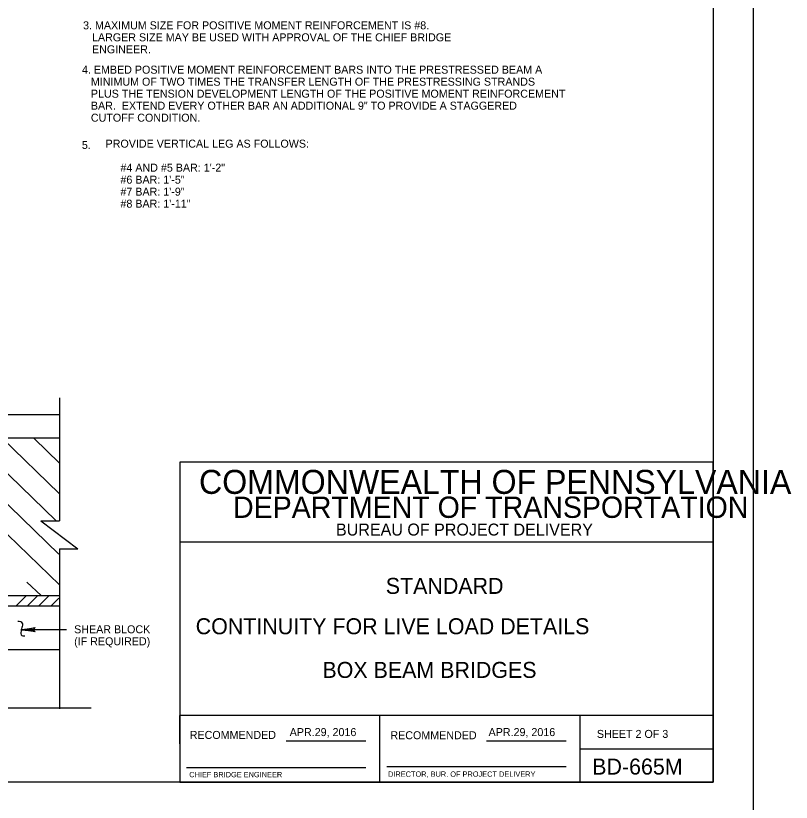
# Model space of a CAD drawing. Extents: x 641517 to 642372, y 298537 to 300319.
# Drawn here: x 642081.6 to 642372.3, y 299138.1 to 299433 of the extents above; entities that cross this region are included whole.
import ezdxf

# ---------------------------------------------------------------- set-up
doc = ezdxf.new("R2010")
doc.units = 0
for name, color, linetype in [('1', 7, 'Continuous'), ('2', 7, 'Continuous'), ('3', 7, 'Continuous'), ('PLT-BNDY', 7, 'Continuous')]:
    doc.layers.add(name, color=color, linetype=linetype)

msp = doc.modelspace()

# ---------------------------------------------------------------- linework, layer by layer
at = {"layer": '1'}
msp.add_spline([(642082.42, 299206.01), (642083.39, 299205.93), (642083.91, 299205.43), (642084.12, 299204.52), (642083.85, 299203.66), (642083.67, 299202.74), (642083.52, 299201.83), (642083.62, 299200.92), (642084.3, 299200.52), (642085.03, 299200.52)], degree=3, dxfattribs=at)
at = {"layer": '2'}
for p, q in [((642343.05, 299709.62), (642343.05, 299145.62)), ((642097.96, 299289.82), (642097.96, 299243.68)), ((641895.27, 299283.53), (642097.96, 299283.53)), ((642097.96, 299274.67), (642037.19, 299274.67)), ((642097.96, 299219.62), (642041.23, 299274.54)), ((642097.79, 299231.2), (642052.95, 299274.61)), ((642096.7, 299243.67), (642064.74, 299274.6)), ((642097.94, 299253.88), (642076.56, 299274.58)), ((642098.01, 299265.23), (642088.45, 299274.48)), ((642343.05, 299265.62), (642143.05, 299265.62)), ((642143.05, 299265.62), (642143.05, 299145.62)), ((642343.05, 299145.62), (642343.05, 299265.62)), ((642091.06, 299243.68), (642097.96, 299243.68)), ((642091.06, 299243.68), (642104.86, 299233.18)), ((642097.96, 299233.18), (642097.96, 299173.17)), ((642097.96, 299233.18), (642104.86, 299233.18)), ((642343.05, 299235.62), (642143.05, 299235.62)), ((642091.1, 299215.64), (642085.77, 299220.69)), ((642037.19, 299215.64), (642097.96, 299215.64)), ((642081.76, 299211.74), (642085.66, 299215.64)), ((642086, 299211.74), (642089.9, 299215.64)), ((642090.24, 299211.74), (642094.14, 299215.64)), ((642094.87, 299211.74), (642097.8, 299214.67)), ((642041.09, 299211.74), (642097.96, 299211.74)), ((642100.61, 299202.83), (642084.05, 299202.83)), ((641895.27, 299195.43), (642097.96, 299195.43)), ((642007.73, 299173.52), (642109.86, 299173.52)), ((642343.05, 299170.62), (642143.05, 299170.62)), ((642143.05, 299160.05), (642143.05, 299170.62)), ((642218.05, 299145.62), (642218.05, 299170.62)), ((642293.05, 299170.62), (642293.05, 299145.62)), ((642183.01, 299161.12), (642212.78, 299161.12)), ((642258.01, 299161.12), (642287.92, 299161.12)), ((642293.05, 299158.12), (642343.05, 299158.12)), ((642145.55, 299151.12), (642212.78, 299151.12)), ((642220.67, 299151.5), (642287.92, 299151.5)), ((642343.05, 299145.62), (641557.05, 299145.62)), ((642143.05, 299145.62), (642343.05, 299145.62))]:
    msp.add_line(p, q, dxfattribs=at)
msp.add_lwpolyline([(642088.66, 299202.25), (642088.49, 299202.58), (642084.05, 299202.83), (642088.66, 299202.25), (642088.9, 299202.04), (642084.05, 299202.83), (642088.49, 299203.05), (642088.65, 299203.38), (642084.05, 299202.83), (642088.9, 299203.6), (642088.65, 299203.38)], dxfattribs=at)
at = {"layer": 'PLT-BNDY'}
msp.add_lwpolyline([(641517.05, 299724.62), (642358.05, 299724.62), (642358.05, 299130.62), (641517.05, 299130.62)], close=True, dxfattribs=at)

# ---------------------------------------------------------------- texts
at = {"layer": '1'}
for s, p in [('PROVIDE VERTICAL LEG AS FOLLOWS:', (642115.28, 299383.56)), ('     #4 AND #5 BAR: 1\'-2"', (642115.28, 299374.56)), ('     #6 BAR: 1\'-5"', (642115.28, 299370.06)), ('     #7 BAR: 1\'-9"', (642115.28, 299365.56)), ('     #8 BAR: 1\'-11"', (642115.28, 299361.06))]:
    msp.add_text(s, height=2.9999, dxfattribs=at).set_placement(p)
at = {"layer": '2'}
for s, height, p in [('3. MAXIMUM SIZE FOR POSITIVE MOMENT REINFORCEMENT IS #8.', 3, (642106.84, 299427.93)), ('   LARGER SIZE MAY BE USED WITH APPROVAL OF THE CHIEF BRIDGE', 3, (642106.84, 299423.43)), ('   ENGINEER.', 3, (642106.84, 299418.93)), ('4. EMBED POSITIVE MOMENT REINFORCEMENT BARS INTO THE PRESTRESSED BEAM A', 3, (642106.42, 299411.3)), ('   MINIMUM OF TWO TIMES THE TRANSFER LENGTH OF THE PRESTRESSING STRANDS', 3, (642106.42, 299406.8)), ('   PLUS THE TENSION DEVELOPMENT LENGTH OF THE POSITIVE MOMENT REINFORCEMENT', 3, (642106.42, 299402.3)), ('   BAR.  EXTEND EVERY OTHER BAR AN ADDITIONAL 9" TO PROVIDE A STAGGERED', 3, (642106.42, 299397.8)), ('   CUTOFF CONDITION.', 3, (642106.42, 299393.3)), ('COMMONWEALTH OF PENNSYLVANIA', 9, (642150.3, 299253.75)), ('DEPARTMENT OF TRANSPORTATION', 8.0002, (642163.05, 299244.75)), ('BUREAU OF PROJECT DELIVERY', 4.5, (642201.64, 299238.12)), ('STANDARD', 6, (642220.3, 299216.25)), ('CONTINUITY FOR LIVE LOAD DETAILS', 6, (642149.05, 299201.12)), ('BOX BEAM BRIDGES', 6, (642196.55, 299184.75)), ('APR.29, 2016', 3, (642184.29, 299162.94)), ('APR.29, 2016', 3, (642258.83, 299162.94)), ('SHEET 2 OF 3', 3, (642299.42, 299162.25)), ('RECOMMENDED', 3, (642146.82, 299161.87)), ('BD-665M', 6, (642297.67, 299148.5)), ('CHIEF BRIDGE ENGINEER', 2.0002, (642146.64, 299147.5)), ('DIRECTOR, BUR. OF PROJECT DELIVERY', 2.0002, (642221.15, 299147.68))]:
    msp.add_text(s, height=height, dxfattribs=at).set_placement(p)
msp.add_text('RECOMMENDED', height=3, rotation=360, dxfattribs=at).set_placement((642222.03, 299161.75))
at = {"layer": '3'}
for s, height, p in [('5.', 2.997, (642106.39, 299383.07)), ('SHEAR BLOCK', 2.999, (642103.5, 299201.48)), ('(IF REQUIRED)', 2.999, (642103.5, 299196.98))]:
    msp.add_text(s, height=height, dxfattribs=at).set_placement(p)

doc.saveas('drawing.dxf')
